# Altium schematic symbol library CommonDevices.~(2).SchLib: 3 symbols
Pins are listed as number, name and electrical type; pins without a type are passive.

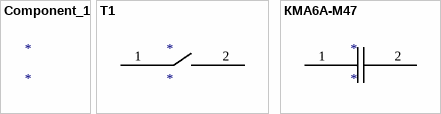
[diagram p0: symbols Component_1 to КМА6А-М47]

## Component_1
designator *

## T1
designator *
pins: 1, 2

## КМА6А-М47
designator *
pins: 1, 2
